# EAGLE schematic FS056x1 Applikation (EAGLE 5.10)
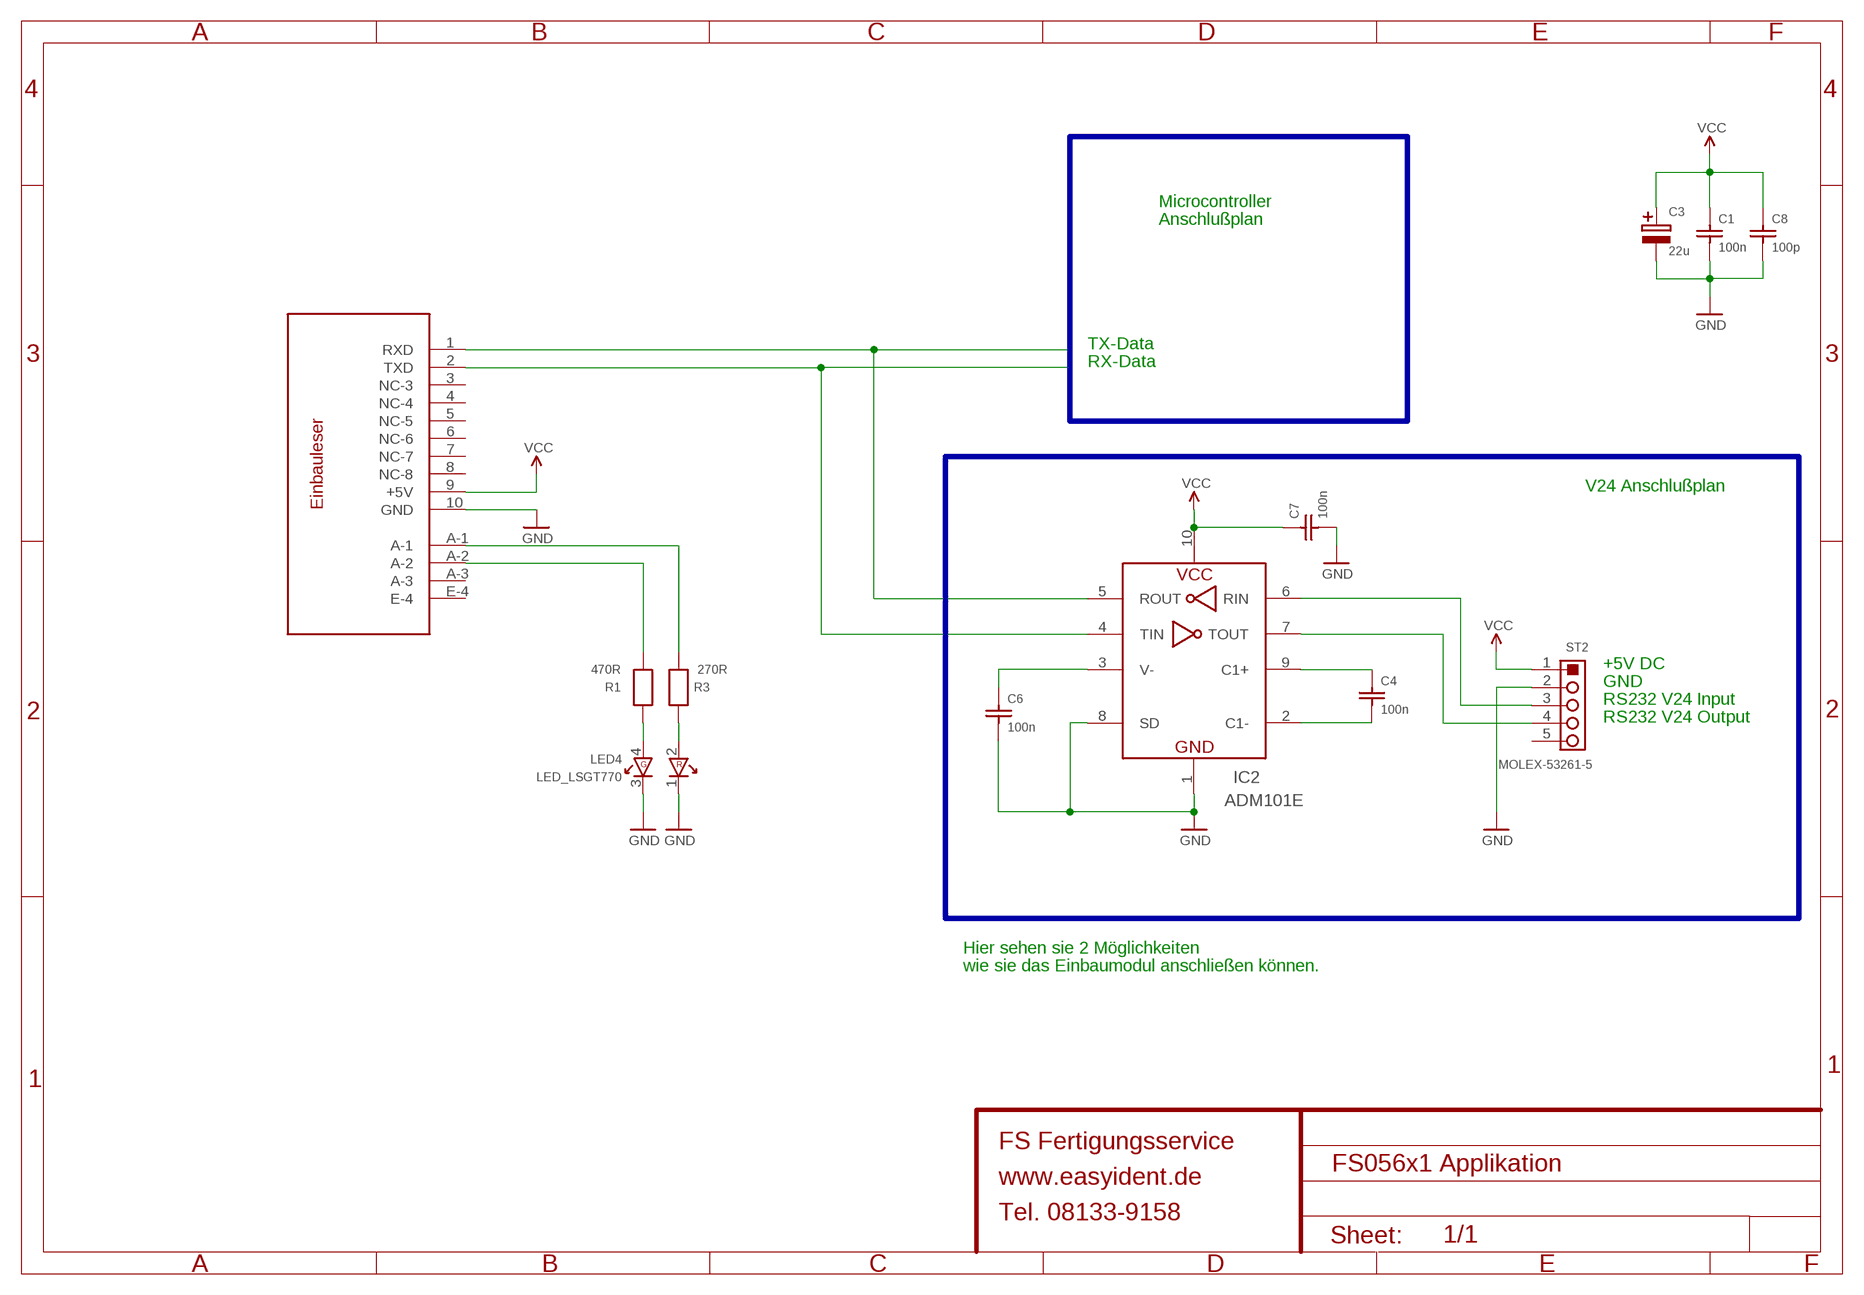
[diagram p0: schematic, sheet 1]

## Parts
C1  100n  C-0603  [0603]
C3  22u  C-TAJA  [TAJA]
C4  100n  C-0603  [0603]
C6  100n  C-0603  [0603]
C7  100n  C-0603  [0603]
C8  100p  C-0603  [0603]
IC2  ADM101E  [µSOIC-10]
LED4  LED_LSGT770  [LED_LSG-T770]
MODUL1  PHG-LESER  [PHG-LESER]
R1  470R  R-0603  [0603]
R3  270R  R-0603  [0603]
ST2  MOLEX-53261-5  [MOLEX-53261-5]

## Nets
GND: C1.P$2 C3.M-(-) C6.P$2 C7.P$2 C8.P$2 IC2.1(GND) IC2.8(SD) LED4.1(C1-P1) LED4.3(C2-P3) MODUL1.10(GND) ST2.2
LED-GRÜN: MODUL1.A-2 R1.P$1
LED-ROT: MODUL1.A-1 R3.P$1
N$3: LED4.4(A2-P4) R1.P$2
N$4: LED4.2(A1-P2) R3.P$2
N$8: C4.P$1 IC2.9(C1+)
N$11: C4.P$2 IC2.2(C1-)
N$12: C6.P$1 IC2.3(V-)
RX-V24: IC2.6(RIN) ST2.3
RXD_TTL: IC2.5(ROUT) MODUL1.1(RXD)
TX-V24: IC2.7(TOUT) ST2.4
TXD_TTL: IC2.4(TIN) MODUL1.2(TXD)
VCC: C1.P$1 C3.P+(+) C7.P$1 C8.P$1 IC2.10(VCC) MODUL1.9(+5V) ST2.1
Unconnected: MODUL1.3(NC-3) MODUL1.4(NC-4) MODUL1.5(NC-5) MODUL1.6(NC-6) MODUL1.7(NC-7) MODUL1.8(NC-8) MODUL1.A-3 MODUL1.E-4 ST2.5

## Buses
B$1
B$2

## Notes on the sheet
- Microcontroller
- Anschlußplan
- TX-Data
- RX-Data
- V24 Anschlußplan
- +5V DC
- GND
- RS232 V24 Input
- RS232 V24 Output
- Hier sehen sie 2 Möglichkeiten
- wie sie das Einbaumodul anschließen können.

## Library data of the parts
C1 C4 C6-C8 = 5-FS-Library:C-0603
C3 = 5-FS-Kondensatoren:C-TAJA
IC2 = 5-FS-Library:ADM101E
LED4 = 5-FS-Library:LED_LSGT770
MODUL1 = 5-FS-Library:PHG-LESER
R1 R3 = 5-FS-Library:R-0603
ST2 = 5-FS-Library:MOLEX-53261-5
